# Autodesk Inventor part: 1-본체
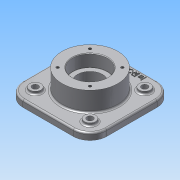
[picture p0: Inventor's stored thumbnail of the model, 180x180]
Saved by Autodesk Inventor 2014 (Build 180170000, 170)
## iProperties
Created: 2015-09
Part Number: 1-본체
Material: 알루미늄 6061
Document SubType Name: Modeling
Designer: study
Density: 2.71 g/cm^3
Appearance: 알루미늄 - 평지
Author: study
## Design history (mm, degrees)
sketch "스케치1"
  geometry: L1 (-75, 75)-(75, 75); L2 (75, 75)-(75, -75); L3 (75, -75)-(-75, -75); L4 (-75, -75)-(-75, 75); L5 (-75, 75)-(75, -75); L6 (75, 75)-(-75, -75); 1 further point
  constraints: 12 end point, 2 midpoint, 2 parallel, 1 horizontal, 1 perpendicular
  dimensions: "d0" = 150 distance of L1.start L1.end; "d1" = 150 distance of L1.end L2.end
extrude "돌출1" new body sketch "스케치1" distance "d2" = 12; taper "d3" = 0 deg
fillet "모깎기1" dims "d4" = 30
sketch "스케치2"
  geometry: C1 r 50 at (0, 0); 1 further point
  constraints: 1 centre point, 1 coincident
  dimensions: "d5" = 100 diameter of C1
extrude "돌출2" join sketch "스케치2" distance "d6" = 35; taper "d7" = 0 deg
sketch "스케치3"
  geometry: C1 r 50 at (0, 0) reference; 1 further point
extrude "돌출3" join sketch "스케치3" distance "d8" = 23; taper "d9" = 0 deg
sketch "스케치4"
  geometry: L1 (49, -49)-(-49, -49); L2 (-49, -49)-(-49, 49); L3 (-49, 49)-(49, 49); L4 (49, 49)-(49, -49); C1 r 50 at (0, 0) reference; C2 r 10 at (49, 49); C3 r 10 at (-49, -49); C4 r 10 at (49, -49); C5 r 10 at (-49, 49); 2 further points
  constraints: 8 end point, 5 coincident, 4 centre point, 3 equal radius, 1 midpoint, 1 vertical alignment, 9 other
  dimensions: "d10" = 98 distance of L2.end L3.end; "d11" = 20 diameter of C5
extrude "돌출4" join sketch "스케치4" distance "d12" = 5; taper "d13" = 0 deg
hole "구멍1" diameter "d16" = 45; stored, may be unused: countersink angle "d20" = 90 deg, drill point angle "d22" = 118 deg; dims "d14" = 10, "d15" = 10, "d17" = 6, "d18" = 62, "d19" = 22, "d21" = 8
hole "구멍2" diameter "d25" = 45; stored, may be unused: countersink angle "d29" = 90 deg, drill point angle "d31" = 118 deg; dims "d23" = 10, "d24" = 10, "d26" = 6, "d27" = 62, "d28" = 22, "d30" = 8
sketch "스케치5"
  geometry: C1 r 10 at (0, 0) reference; C2 r 10 at (98, 0) reference; C3 r 10 at (98, -98) reference; C4 r 10 at (0, -98) reference; 5 further points
  constraints: 4 coincident
hole "구멍3" sketch "스케치5" at (0, 0), (0, -98), (98, -98), (98, 0) diameter "d32" = 11; stored, may be unused: countersink angle "d36" = 90 deg, drill point angle "d38" = 118 deg; dims "d33" = 6, "d34" = 62, "d35" = 22, "d37" = 8
sketch "스케치6"
  geometry: L1 (-41, 0)-(0, 0); L2 (0, 0)-(-28.991, 28.991); C1 r 50 at (0, 0) reference; A1 r 41 centre (0, 0) between (-41, 0) and (-28.991, 28.991); 4 further points
  constraints: 5 point on circle, 4 end point, 2 coincident, 2 horizontal alignment, 1 centre point, 1 horizontal, 1 vertical alignment
  dimensions: "d39" = 82 diameter of A1; "d40" = 45 deg angle of L1 L2
hole "구멍4" sketch "스케치6" at (-28.991, 28.991), (-28.991, -28.991), (28.991, -28.991), (28.991, 28.991) diameter "d41" = 4.917; stored, may be unused: countersink angle "d45" = 90 deg, drill point angle "d47" = 118 deg; dims "d42" = 10, "d43" = 62, "d44" = 22, "d46" = 13
sketch "스케치7"
  geometry: L1 (-41, 0)-(0, 0); L2 (0, 0)-(-28.991, 28.991); C1 r 50 at (0, 0) reference; A1 r 41 centre (0, 0) between (-41, 0) and (-28.991, 28.991); 4 further points
  constraints: 5 point on circle, 4 end point, 2 coincident, 2 horizontal alignment, 1 centre point, 1 horizontal, 1 vertical alignment
  dimensions: "d48" = 82 diameter of A1; "d49" = 45 deg angle of L1 L2
hole "구멍5" sketch "스케치7" at (-28.991, 28.991), (-28.991, -28.991), (28.991, -28.991), (28.991, 28.991) diameter "d50" = 4.917; stored, may be unused: countersink angle "d54" = 90 deg, drill point angle "d56" = 118 deg; dims "d51" = 10, "d52" = 62, "d53" = 22, "d55" = 13
sketch "스케치8"
  geometry: C1 r 50 at (0, 0) reference; 1 further point
  constraints: 1 vertical alignment, 1 other
  dimensions: "d57" = 65 distance of C1.centre point (0, 65)
feature "엠보싱1" sketch "스케치8" dims "d0" = 150, "d1" = 150, "d58" = 1, "d59" = 0
fillet "모깎기2" dims "d60" = 3, "d64" = 0.3
chamfer "모따기1" distance "d61" = 1; stored, may be unused: second distance "d62" = 2, angle "d63" = 45 deg
node "솔리드1"
